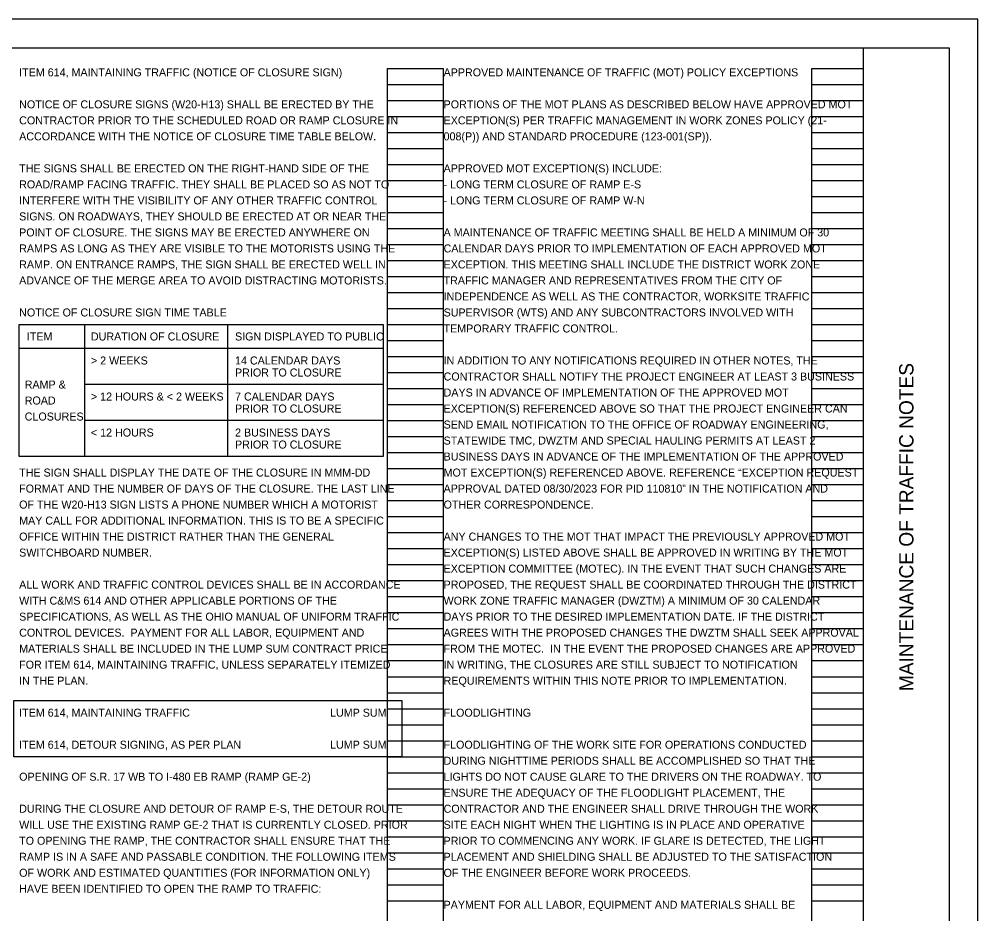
# Model space of a CAD drawing. Extents: x 0 to 34, y -9.1 to 22.
# Drawn here: x 17.24 to 34, y 6.35 to 22 of the extents above; entities that cross this region are included whole.
import ezdxf

# ---------------------------------------------------------------- set-up
doc = ezdxf.new("R2010")
doc.units = 0
for name, color, linetype in [('SC_Scratch1', 7, 'Continuous'), ('SH_Border', 7, 'Continuous'), ('SH_Cut_Line', 7, 'Continuous'), ('SH_Data', 7, 'Continuous'), ('SH_Text', 7, 'Continuous')]:
    doc.layers.add(name, color=color, linetype=linetype)

msp = doc.modelspace()

# ---------------------------------------------------------------- linework, layer by layer
at = {"layer": 'SC_Scratch1'}
msp.add_lwpolyline([(17.145, 10.084), (23.928, 10.084), (23.928, 9.1), (17.145, 9.1)], close=True, dxfattribs=at)
at = {"layer": 'SH_Border'}
msp.add_line((32, 0.5), (32, 21.5), dxfattribs=at)
msp.add_lwpolyline([(1.5, 21.5), (33.5, 21.5), (33.5, 0.5), (1.5, 0.5)], close=True, dxfattribs=at)
at = {"layer": 'SH_Cut_Line'}
msp.add_lwpolyline([(0, 0), (34, 0), (34, 22), (0, 22)], close=True, dxfattribs=at)
at = {"layer": 'SH_Data'}
for p, q in [((23.68, 0.98), (23.68, 21.14)), ((23.68, 21.14), (24.66, 21.14)), ((24.66, 0.98), (24.66, 21.14)), ((31.1, 0.98), (31.1, 21.14)), ((31.1, 21.14), (32, 21.14)), ((32, 0.98), (32, 21.14)), ((23.68, 20.86), (24.66, 20.86)), ((31.1, 20.86), (32, 20.86)), ((23.68, 20.58), (24.66, 20.58)), ((31.1, 20.58), (32, 20.58)), ((23.68, 20.3), (24.66, 20.3)), ((31.1, 20.3), (32, 20.3)), ((23.68, 20.02), (24.66, 20.02)), ((31.1, 20.02), (32, 20.02)), ((23.68, 19.74), (24.66, 19.74)), ((31.1, 19.74), (32, 19.74)), ((23.68, 19.46), (24.66, 19.46)), ((31.1, 19.46), (32, 19.46)), ((23.68, 19.18), (24.66, 19.18)), ((31.1, 19.18), (32, 19.18)), ((23.68, 18.9), (24.66, 18.9)), ((31.1, 18.9), (32, 18.9)), ((23.68, 18.62), (24.66, 18.62)), ((31.1, 18.62), (32, 18.62)), ((23.68, 18.34), (24.66, 18.34)), ((31.1, 18.34), (32, 18.34)), ((23.68, 18.06), (24.66, 18.06)), ((31.1, 18.06), (32, 18.06)), ((23.68, 17.78), (24.66, 17.78)), ((31.1, 17.78), (32, 17.78)), ((23.68, 17.5), (24.66, 17.5)), ((31.1, 17.5), (32, 17.5)), ((23.68, 17.22), (24.66, 17.22)), ((31.1, 17.22), (32, 17.22)), ((23.68, 16.94), (24.66, 16.94)), ((31.1, 16.94), (32, 16.94)), ((23.68, 16.66), (24.66, 16.66)), ((31.1, 16.66), (32, 16.66)), ((23.68, 16.38), (24.66, 16.38)), ((31.1, 16.38), (32, 16.38)), ((23.68, 16.1), (24.66, 16.1)), ((31.1, 16.1), (32, 16.1)), ((23.68, 15.82), (24.66, 15.82)), ((31.1, 15.82), (32, 15.82)), ((23.68, 15.54), (24.66, 15.54)), ((31.1, 15.54), (32, 15.54)), ((23.68, 15.26), (24.66, 15.26)), ((31.1, 15.26), (32, 15.26)), ((23.68, 14.98), (24.66, 14.98)), ((31.1, 14.98), (32, 14.98)), ((23.68, 14.7), (24.66, 14.7)), ((31.1, 14.7), (32, 14.7)), ((23.68, 14.42), (24.66, 14.42)), ((31.1, 14.42), (32, 14.42)), ((23.68, 14.14), (24.66, 14.14)), ((31.1, 14.14), (32, 14.14)), ((23.68, 13.86), (24.66, 13.86)), ((31.1, 13.86), (32, 13.86)), ((23.68, 13.58), (24.66, 13.58)), ((31.1, 13.58), (32, 13.58)), ((23.68, 13.3), (24.66, 13.3)), ((31.1, 13.3), (32, 13.3)), ((23.68, 13.02), (24.66, 13.02)), ((31.1, 13.02), (32, 13.02)), ((23.68, 12.74), (24.66, 12.74)), ((31.1, 12.74), (32, 12.74)), ((23.68, 12.46), (24.66, 12.46)), ((31.1, 12.46), (32, 12.46)), ((23.68, 12.18), (24.66, 12.18)), ((31.1, 12.18), (32, 12.18)), ((23.68, 11.9), (24.66, 11.9)), ((31.1, 11.9), (32, 11.9)), ((23.68, 11.62), (24.66, 11.62)), ((31.1, 11.62), (32, 11.62)), ((23.68, 11.34), (24.66, 11.34)), ((31.1, 11.34), (32, 11.34)), ((23.68, 11.06), (24.66, 11.06)), ((31.1, 11.06), (32, 11.06)), ((23.68, 10.78), (24.66, 10.78)), ((31.1, 10.78), (32, 10.78)), ((23.68, 10.5), (24.66, 10.5)), ((31.1, 10.5), (32, 10.5)), ((23.68, 10.22), (24.66, 10.22)), ((31.1, 10.22), (32, 10.22)), ((23.68, 9.94), (24.66, 9.94)), ((31.1, 9.94), (32, 9.94)), ((23.68, 9.66), (24.66, 9.66)), ((31.1, 9.66), (32, 9.66)), ((23.68, 9.38), (24.66, 9.38)), ((31.1, 9.38), (32, 9.38)), ((23.68, 9.1), (24.66, 9.1)), ((31.1, 9.1), (32, 9.1)), ((23.68, 8.82), (24.66, 8.82)), ((31.1, 8.82), (32, 8.82)), ((23.68, 8.54), (24.66, 8.54)), ((31.1, 8.54), (32, 8.54)), ((23.68, 8.26), (24.66, 8.26)), ((31.1, 8.26), (32, 8.26)), ((23.68, 7.98), (24.66, 7.98)), ((31.1, 7.98), (32, 7.98)), ((23.68, 7.7), (24.66, 7.7)), ((31.1, 7.7), (32, 7.7)), ((23.68, 7.42), (24.66, 7.42)), ((31.1, 7.42), (32, 7.42)), ((23.68, 7.14), (24.66, 7.14)), ((31.1, 7.14), (32, 7.14)), ((23.68, 6.86), (24.66, 6.86)), ((31.1, 6.86), (32, 6.86)), ((23.68, 6.58), (24.66, 6.58)), ((31.1, 6.58), (32, 6.58))]:
    msp.add_line(p, q, dxfattribs=at)
at = {"layer": 'SH_Text'}
for p, q in [((18.39, 14.35), (18.39, 16.66)), ((20.888, 14.35), (20.888, 16.66)), ((23.602, 16.24), (17.24, 16.24)), ((23.602, 15.61), (18.39, 15.61)), ((23.602, 14.98), (18.39, 14.98))]:
    msp.add_line(p, q, dxfattribs=at)
msp.add_lwpolyline([(17.24, 16.66), (23.602, 16.66), (23.602, 14.35), (17.24, 14.35)], close=True, dxfattribs=at)

# ---------------------------------------------------------------- texts
at = {"layer": 'SH_Data'}
msp.add_text('MAINTENANCE OF TRAFFIC NOTES', height=0.25, rotation=90, dxfattribs=at).set_placement((32.875, 10.247))
at = {"layer": 'SH_Text'}
for s, p in [('ITEM 614, MAINTAINING TRAFFIC (NOTICE OF CLOSURE SIGN)', (17.24, 21)), ('APPROVED MAINTENANCE OF TRAFFIC (MOT) POLICY EXCEPTIONS', (24.66, 21)), ('NOTICE OF CLOSURE SIGNS (W20-H13) SHALL BE ERECTED BY THE ', (17.24, 20.44)), ('PORTIONS OF THE MOT PLANS AS DESCRIBED BELOW HAVE APPROVED MOT ', (24.66, 20.44)), ('CONTRACTOR PRIOR TO THE SCHEDULED ROAD OR RAMP CLOSURE IN ', (17.24, 20.16)), ('EXCEPTION(S) PER TRAFFIC MANAGEMENT IN WORK ZONES POLICY (21-', (24.66, 20.16)), ('ACCORDANCE WITH THE NOTICE OF CLOSURE TIME TABLE BELOW. ', (17.24, 19.88)), ('008(P)) AND STANDARD PROCEDURE (123-001(SP)). ', (24.66, 19.88)), ('THE SIGNS SHALL BE ERECTED ON THE RIGHT-HAND SIDE OF THE ', (17.24, 19.32)), ('APPROVED MOT EXCEPTION(S) INCLUDE:', (24.66, 19.32)), ('ROAD/RAMP FACING TRAFFIC. THEY SHALL BE PLACED SO AS NOT TO ', (17.24, 19.04)), ('- LONG TERM CLOSURE OF RAMP E-S', (24.66, 19.04)), ('INTERFERE WITH THE VISIBILITY OF ANY OTHER TRAFFIC CONTROL ', (17.24, 18.76)), ('- LONG TERM CLOSURE OF RAMP W-N', (24.66, 18.76)), ('SIGNS. ON ROADWAYS, THEY SHOULD BE ERECTED AT OR NEAR THE ', (17.24, 18.48)), ('POINT OF CLOSURE. THE SIGNS MAY BE ERECTED ANYWHERE ON ', (17.24, 18.2)), ('A MAINTENANCE OF TRAFFIC MEETING SHALL BE HELD A MINIMUM OF 30 ', (24.66, 18.2)), ('RAMPS AS LONG AS THEY ARE VISIBLE TO THE MOTORISTS USING THE ', (17.24, 17.92)), ('CALENDAR DAYS PRIOR TO IMPLEMENTATION OF EACH APPROVED MOT ', (24.66, 17.92)), ('RAMP. ON ENTRANCE RAMPS, THE SIGN SHALL BE ERECTED WELL IN ', (17.24, 17.64)), ('EXCEPTION. THIS MEETING SHALL INCLUDE THE DISTRICT WORK ZONE ', (24.66, 17.64)), ('ADVANCE OF THE MERGE AREA TO AVOID DISTRACTING MOTORISTS. ', (17.24, 17.36)), ('TRAFFIC MANAGER AND REPRESENTATIVES FROM THE CITY OF ', (24.66, 17.36)), ('INDEPENDENCE AS WELL AS THE CONTRACTOR, WORKSITE TRAFFIC ', (24.66, 17.08)), ('NOTICE OF CLOSURE SIGN TIME TABLE', (17.24, 16.8)), ('SUPERVISOR (WTS) AND ANY SUBCONTRACTORS INVOLVED WITH ', (24.66, 16.8)), ('TEMPORARY TRAFFIC CONTROL. ', (24.66, 16.52)), ('ITEM', (17.374, 16.38)), ('DURATION OF CLOSURE', (18.494, 16.38)), ('SIGN DISPLAYED TO PUBLIC', (21.014, 16.38)), (' 2 WEEKS', (18.604, 15.96)), ('14 CALENDAR DAYS', (21.014, 15.96)), ('IN ADDITION TO ANY NOTIFICATIONS REQUIRED IN OTHER NOTES, THE ', (24.66, 15.96)), ('>', (18.494, 15.96)), ('PRIOR TO CLOSURE', (21.014, 15.75)), ('CONTRACTOR SHALL NOTIFY THE PROJECT ENGINEER AT LEAST 3 BUSINESS ', (24.66, 15.68)), ('RAMP &', (17.337, 15.54)), ('> 12 HOURS & < 2 WEEKS', (18.494, 15.33)), ('7 CALENDAR DAYS', (21.014, 15.33)), ('DAYS IN ADVANCE OF IMPLEMENTATION OF THE APPROVED MOT ', (24.66, 15.4)), ('ROAD', (17.337, 15.26)), ('PRIOR TO CLOSURE', (21.014, 15.12)), ('EXCEPTION(S) REFERENCED ABOVE SO THAT THE PROJECT ENGINEER CAN ', (24.66, 15.12)), ('CLOSURES', (17.337, 14.98)), ('SEND EMAIL NOTIFICATION TO THE OFFICE OF ROADWAY ENGINEERING, ', (24.66, 14.84)), ('<', (18.494, 14.7)), (' 12 HOURS', (18.604, 14.7)), ('2 BUSINESS DAYS', (21.014, 14.7)), ('PRIOR TO CLOSURE', (21.014, 14.49)), ('STATEWIDE TMC, DWZTM AND SPECIAL HAULING PERMITS AT LEAST 2 ', (24.66, 14.56)), ('BUSINESS DAYS IN ADVANCE OF THE IMPLEMENTATION OF THE APPROVED ', (24.66, 14.28)), ('THE SIGN SHALL DISPLAY THE DATE OF THE CLOSURE IN MMM-DD ', (17.24, 14)), ('MOT EXCEPTION(S) REFERENCED ABOVE. REFERENCE “EXCEPTION REQUEST ', (24.66, 14)), ('FORMAT AND THE NUMBER OF DAYS OF THE CLOSURE. THE LAST LINE ', (17.24, 13.72)), ('APPROVAL DATED 08/30/2023 FOR PID 110810” IN THE NOTIFICATION AND ', (24.66, 13.72)), ('OF THE W20-H13 SIGN LISTS A PHONE NUMBER WHICH A MOTORIST ', (17.24, 13.44)), ('OTHER CORRESPONDENCE. ', (24.66, 13.44)), ('MAY CALL FOR ADDITIONAL INFORMATION. THIS IS TO BE A SPECIFIC ', (17.24, 13.16)), ('OFFICE WITHIN THE DISTRICT RATHER THAN THE GENERAL ', (17.24, 12.88)), ('ANY CHANGES TO THE MOT THAT IMPACT THE PREVIOUSLY APPROVED MOT ', (24.66, 12.88)), ('SWITCHBOARD NUMBER.', (17.24, 12.6)), ('EXCEPTION(S) LISTED ABOVE SHALL BE APPROVED IN WRITING BY THE MOT ', (24.66, 12.6)), ('EXCEPTION COMMITTEE (MOTEC). IN THE EVENT THAT SUCH CHANGES ARE ', (24.66, 12.32)), ('ALL WORK AND TRAFFIC CONTROL DEVICES SHALL BE IN ACCORDANCE ', (17.24, 12.04)), ('PROPOSED, THE REQUEST SHALL BE COORDINATED THROUGH THE DISTRICT ', (24.66, 12.04)), ('WITH C&MS 614 AND OTHER APPLICABLE PORTIONS OF THE ', (17.24, 11.76)), ('WORK ZONE TRAFFIC MANAGER (DWZTM) A MINIMUM OF 30 CALENDAR ', (24.66, 11.76)), ('SPECIFICATIONS, AS WELL AS THE OHIO MANUAL OF UNIFORM TRAFFIC ', (17.24, 11.48)), ('DAYS PRIOR TO THE DESIRED IMPLEMENTATION DATE. IF THE DISTRICT ', (24.66, 11.48)), ('CONTROL DEVICES.  PAYMENT FOR ALL LABOR, EQUIPMENT AND ', (17.24, 11.2)), ('AGREES WITH THE PROPOSED CHANGES THE DWZTM SHALL SEEK APPROVAL ', (24.66, 11.2)), ('MATERIALS SHALL BE INCLUDED IN THE LUMP SUM CONTRACT PRICE ', (17.24, 10.92)), ('FROM THE MOTEC.  IN THE EVENT THE PROPOSED CHANGES ARE APPROVED ', (24.66, 10.92)), ('FOR ITEM 614, MAINTAINING TRAFFIC, UNLESS SEPARATELY ITEMIZED ', (17.24, 10.64)), ('IN WRITING, THE CLOSURES ARE STILL SUBJECT TO NOTIFICATION ', (24.66, 10.64)), ('IN THE PLAN.', (17.24, 10.36)), ('REQUIREMENTS WITHIN THIS NOTE PRIOR TO IMPLEMENTATION.', (24.66, 10.36)), ('ITEM 614, MAINTAINING TRAFFIC', (17.24, 9.8)), ('LUMP SUM', (22.675, 9.8)), ('FLOODLIGHTING', (24.66, 9.8)), ('ITEM 614, DETOUR SIGNING, AS PER PLAN', (17.24, 9.24)), ('LUMP SUM', (22.675, 9.24)), ('FLOODLIGHTING OF THE WORK SITE FOR OPERATIONS CONDUCTED ', (24.66, 9.24)), ('DURING NIGHTTIME PERIODS SHALL BE ACCOMPLISHED SO THAT THE ', (24.66, 8.96)), ('OPENING OF S.R. 17 WB TO I-480 EB RAMP (RAMP GE-2)', (17.24, 8.68)), ('LIGHTS DO NOT CAUSE GLARE TO THE DRIVERS ON THE ROADWAY. TO ', (24.66, 8.68)), ('ENSURE THE ADEQUACY OF THE FLOODLIGHT PLACEMENT, THE ', (24.66, 8.4)), ('DURING THE CLOSURE AND DETOUR OF RAMP E-S, THE DETOUR ROUTE ', (17.24, 8.12)), ('CONTRACTOR AND THE ENGINEER SHALL DRIVE THROUGH THE WORK ', (24.66, 8.12)), ('WILL USE THE EXISTING RAMP GE-2 THAT IS CURRENTLY CLOSED. PRIOR ', (17.24, 7.84)), ('SITE EACH NIGHT WHEN THE LIGHTING IS IN PLACE AND OPERATIVE ', (24.66, 7.84)), ('TO OPENING THE RAMP, THE CONTRACTOR SHALL ENSURE THAT THE ', (17.24, 7.56)), ('PRIOR TO COMMENCING ANY WORK. IF GLARE IS DETECTED, THE LIGHT ', (24.66, 7.56)), ('RAMP IS IN A SAFE AND PASSABLE CONDITION. THE FOLLOWING ITEMS ', (17.24, 7.28)), ('PLACEMENT AND SHIELDING SHALL BE ADJUSTED TO THE SATISFACTION ', (24.66, 7.28)), ('OF WORK AND ESTIMATED QUANTITIES (FOR INFORMATION ONLY) ', (17.24, 7)), ('OF THE ENGINEER BEFORE WORK PROCEEDS.', (24.66, 7)), ('HAVE BEEN IDENTIFIED TO OPEN THE RAMP TO TRAFFIC:', (17.24, 6.72)), ('PAYMENT FOR ALL LABOR, EQUIPMENT AND MATERIALS SHALL BE ', (24.66, 6.44))]:
    msp.add_text(s, height=0.14, dxfattribs=at).set_placement(p)

doc.saveas('drawing.dxf')
